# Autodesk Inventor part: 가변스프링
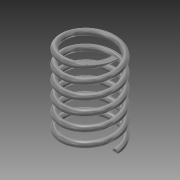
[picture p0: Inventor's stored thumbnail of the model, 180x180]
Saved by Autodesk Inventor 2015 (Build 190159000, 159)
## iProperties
Created: 2015-10
Part Number: 가변스프링
Material: Steel, Mild
Document SubType Name: Modeling
Designer: youjin03
Density: 7.85 g/cm^3
Appearance: Semi-Polished
Mass: 128.859 g
Surface Area: 133.055 cm^2
Volume: 16.4151 cm^3
Author: youjin03
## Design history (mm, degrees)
sketch "Sketch1"
  geometry: L1 (-22.5, 73.25)-(0, 73.25); L2 (0, 73.25)-(0, 0); L3 (0, 0)-(-22.5, 0); L4 (-22.5, 0)-(-22.5, 73.25); C1 r 2.5 at (-22.5, 0); 1 further point
  constraints: 8 end point, 2 coincident, 2 parallel, 1 centre point, 1 horizontal, 1 perpendicular
  dimensions: "d0" = 73.25 distance between parallel lines of L1 L3 (derived); "d1" = 45 diameter of L4 L2; "d2" = 5 diameter of C1
coil "Coil1" sketch "Sketch1" pitch "d3" = 10; turns "d5" = 6; dims "d4" = 73.25 (= d0), "d6" = 0, angle "d7" = 90 deg, angle "d8" = 90 deg, "d9" = 0, "d10" = 0
sketch "Sketch2"
  geometry: L1 (25, 0)-(20, 0) reference; 1 further point
  constraints: 1 horizontal alignment
extrude "Extrusion1" cut sketch "Sketch2" stored distance "d11" = 10; taper "d12" = 0 deg
workplane "Work Plane1"
sketch "Sketch3"
  geometry: L1 (-25, 0)-(-20, 0) reference; 1 further point
  constraints: 1 horizontal alignment
extrude "Extrusion2" cut sketch "Sketch3" stored distance "d13" = 10; taper "d14" = 0 deg
body "Solid1"
node "Project Cut Edges1"
node "Project Cut Edges2"
